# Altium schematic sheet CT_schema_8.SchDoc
size 382 x 278 mm
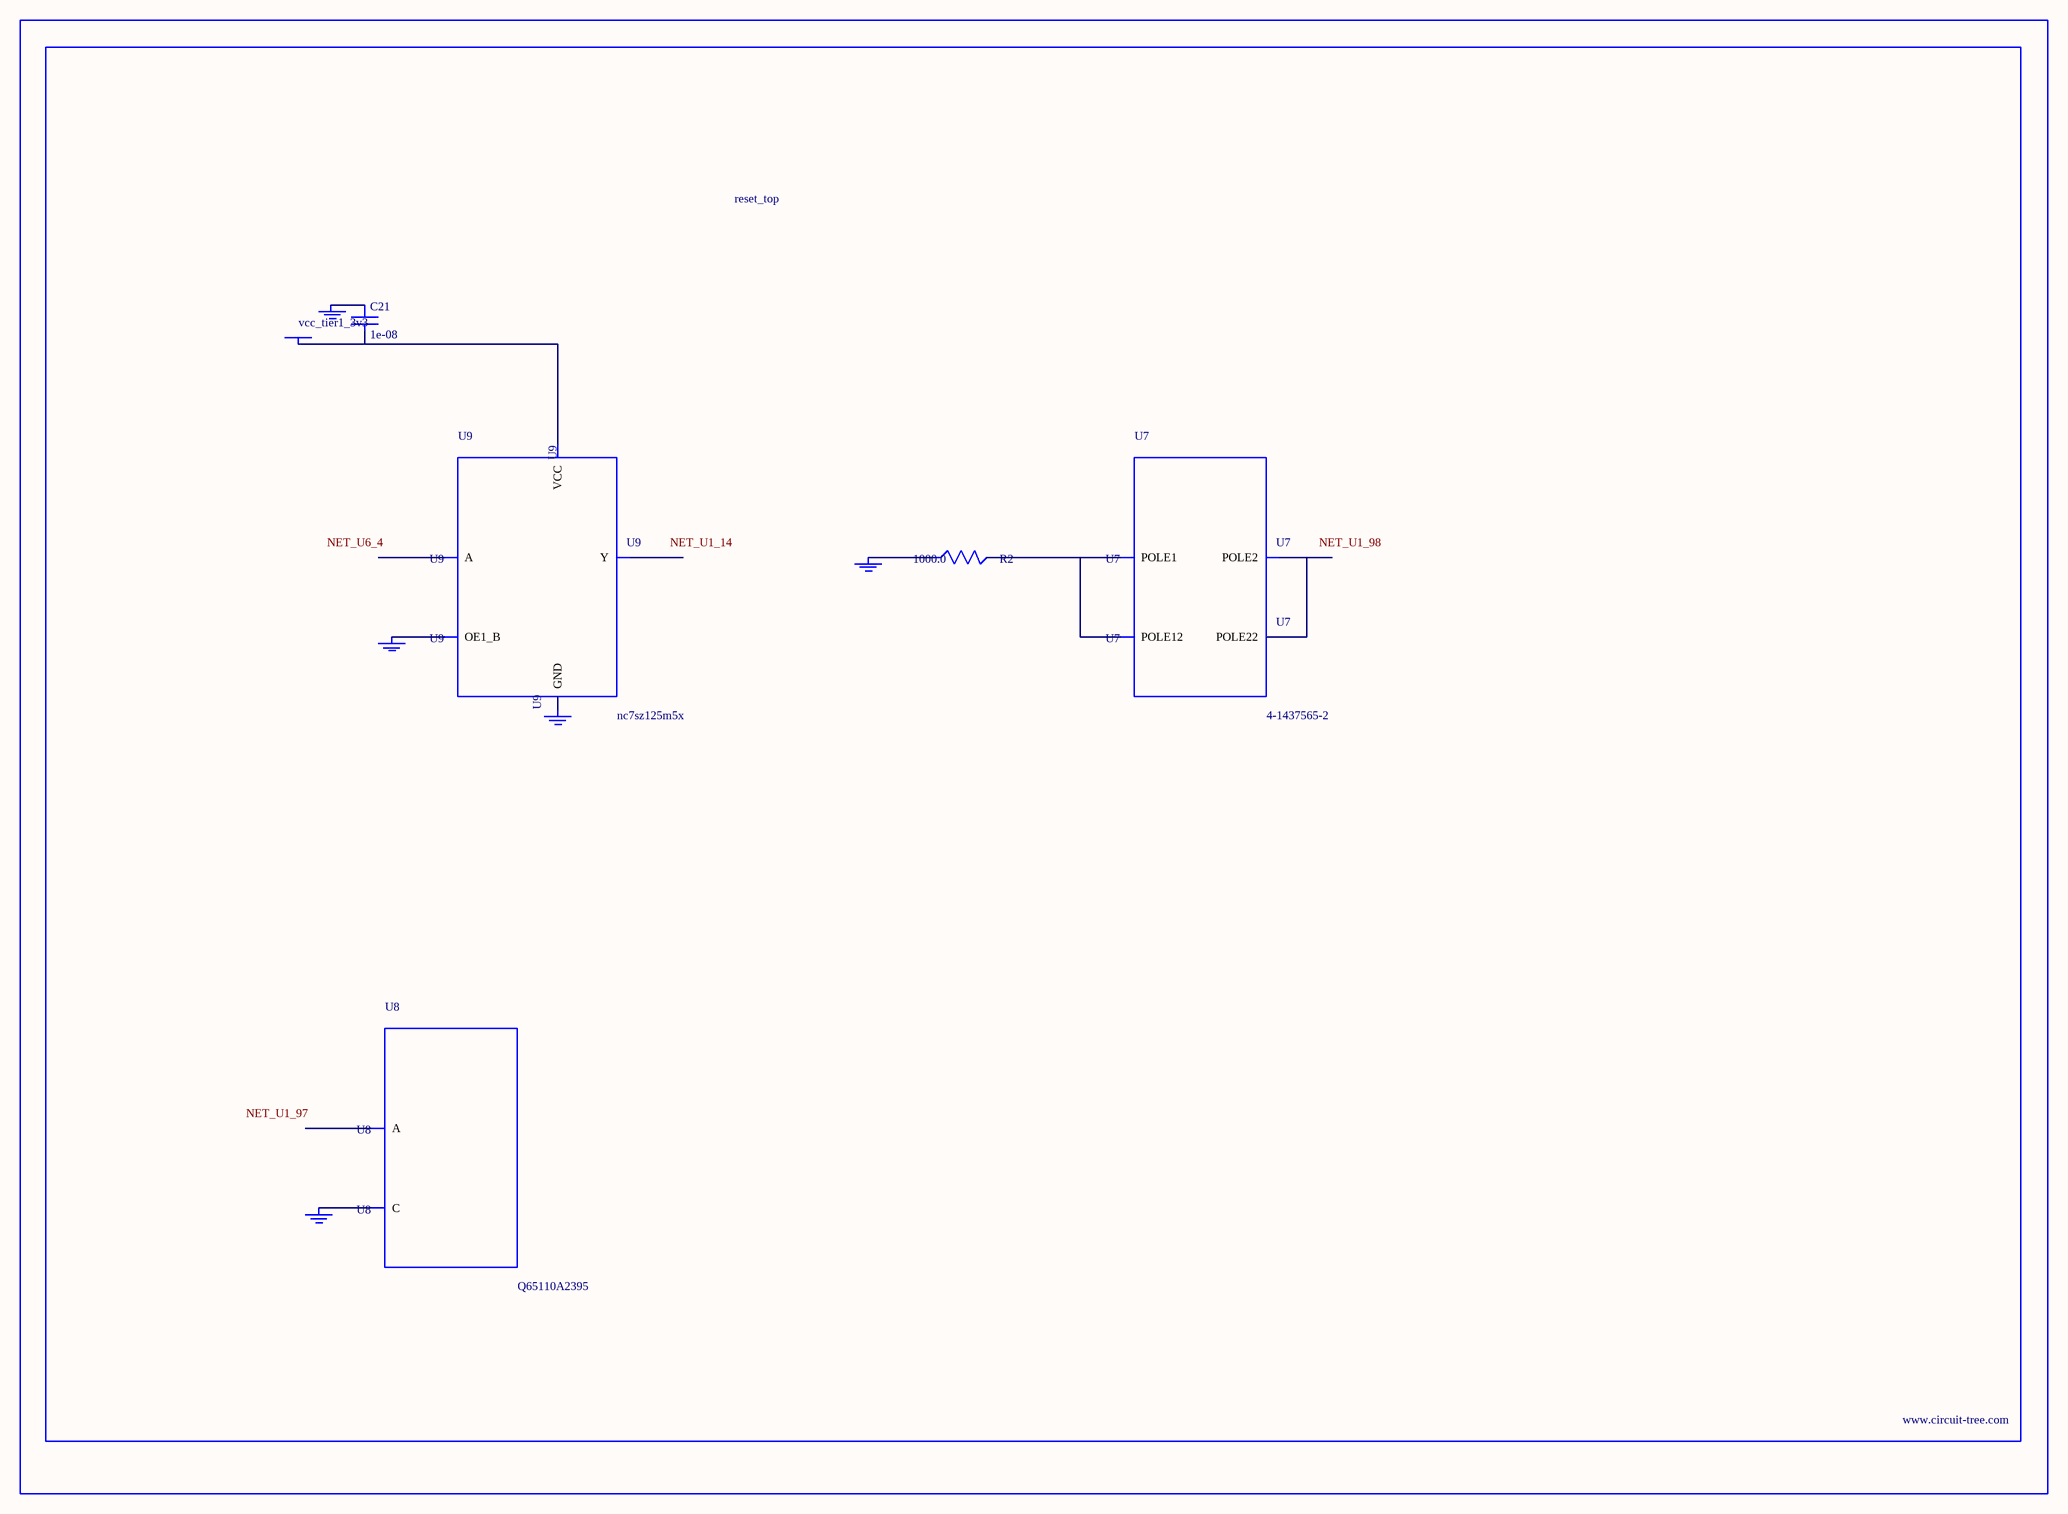
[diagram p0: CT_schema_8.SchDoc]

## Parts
BORDER7  (no value)
C21  1e-08  [C0402]
GND_INSTANCE_7_0  (no value)
GND_INSTANCE_7_1  (no value)
GND_INSTANCE_7_2  (no value)
GND_INSTANCE_7_3  (no value)
GND_INSTANCE_7_4  (no value)
POWER_INSTANCE_7_0  vcc_tier1_3v3
R2  1000.0  [R0603]
U7  4-1437565-2  [SW_4-1437565-2]
U8  Q65110A2395  [LGM67K-G1J2-24-Z]
U9  nc7sz125m5x  [NC7SZ125M5X]

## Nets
NetC21_1: C21.1 GND_INSTANCE_7_2.0(GND)
NetC21_2: C21.2 POWER_INSTANCE_7_0.0(PWR) U9.5(VCC)
NetGND_INSTANCE_7_0_0: GND_INSTANCE_7_0.0(GND) R2.1
NetGND_INSTANCE_7_1_0: GND_INSTANCE_7_1.0(GND) U8.C
NetGND_INSTANCE_7_3_0: GND_INSTANCE_7_3.0(GND) U9.1(OE1_B)
NetGND_INSTANCE_7_4_0: GND_INSTANCE_7_4.0(GND) U9.3(GND)
NetR2_2: R2.2 U7.1(POLE1) U7.2(POLE12)
NetU7_3: U7.3(POLE2) U7.4(POLE22)

Not connected (* = marked no-connect by the designer): U8 A; U9 2(A) 4(Y)

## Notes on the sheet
- Labels drawn without touching a wire or pin: NET_U1_14, NET_U1_97, NET_U1_98, NET_U6_4

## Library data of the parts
BORDER7 = BORDER_PAGE7
C21 = C0402C103K3RAC
GND_INSTANCE_7_0-GND_INSTANCE_7_4 = GND
POWER_INSTANCE_7_0 = PWR
R2 = RC0603JR-071KL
